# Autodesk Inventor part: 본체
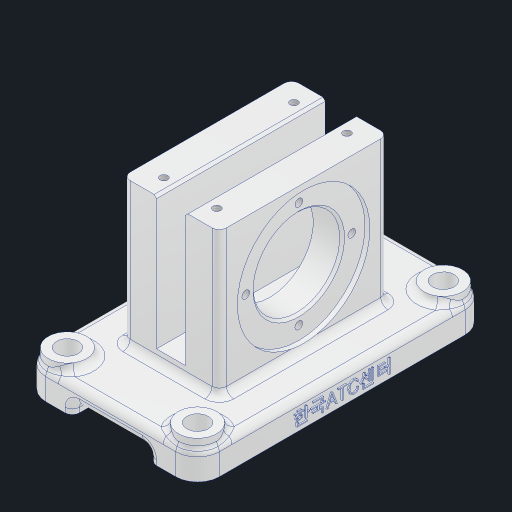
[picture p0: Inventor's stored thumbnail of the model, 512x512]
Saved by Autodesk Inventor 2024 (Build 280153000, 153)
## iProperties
Created: 2025-04
Part Number: 본체
Material: 알루미늄 6061
Document SubType Name: Modeling
Designer: kh_501
Density: 2.7 g/cm^3
Appearance: 알루미늄 - 평지
Mass: 493.657 g
Surface Area: 439.689 cm^2
Volume: 182.836 cm^3
Author: kh_501
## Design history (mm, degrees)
sketch "스케치1"
  geometry: L1 (36, 60)-(-36, 60); L2 (-36, 60)-(-36, -60); L3 (-36, -60)-(36, -60); L4 (36, -60)-(36, 60); L5 (36, 60)-(-36, -60); L6 (-36, 60)-(36, -60); 1 further point
  constraints: 12 end point, 2 midpoint, 2 parallel, 1 horizontal, 1 perpendicular
  dimensions: "d0" = 120 distance of L3.end L1.start; "d1" = 72 distance of L2.end L3.end
extrude "돌출1" new body sketch "스케치1" distance "d2" = 12; taper "d3" = 0 deg
sketch "스케치2"
  geometry: L1 (72, 35)-(12, 35); L2 (12, 35)-(12, -35); L3 (12, -35)-(72, -35); L4 (72, -35)-(72, 35); L5 (12, 60)-(12, -60) reference; L6 (0, 60)-(0, -60) reference; 2 further points
  constraints: 8 end point, 2 midpoint, 2 parallel, 1 horizontal, 1 perpendicular
  dimensions: "d4" = 70 distance of L3.end L1.start; "d5" = 72 distance between parallel lines of L6 L4
extrude "돌출2" join sketch "스케치2" stored distance "d6" = 40; taper "d7" = 0 deg
sketch "스케치3"
  geometry: L1 (14, 60)-(26, 60); L2 (26, 60)-(26, 5); L3 (26, 5)-(14, 5); L4 (14, 5)-(14, 60); L5 (40, 60)-(0, 60) reference; 3 further points
  constraints: 8 end point, 3 midpoint, 2 parallel, 1 horizontal, 1 perpendicular
  dimensions: "d8" = 12 distance from line of point (26, 32.5) L4; "d9" = 55 distance of L1.end L2.end
extrude "돌출3" cut sketch "스케치3" extent not by distance; stored distance "d10" = 0; taper "d11" = 0 deg
sketch "스케치4"
  geometry: L1 (-60, 0)-(60, 0) reference; C1 r 17 at (0, 42); 2 further points
  constraints: 1 centre point, 1 midpoint, 1 vertical alignment
  dimensions: "d12" = 34 diameter of C1; "d13" = 42 distance from line of C1.centre L1
extrude "돌출4" join sketch "스케치4" distance "d14" = 7; taper "d15" = 0 deg
sketch "스케치5"
  geometry: L1 (20, 72)-(20, 12) reference; L2 (-27, 59)-(-27, 25) reference; L3 (-27, 42)-(20, 42); L4 (20, 69.5)-(18, 69.5); L5 (18, 69.5)-(18, 61); L6 (17, 60)-(6, 60); L7 (6, 72)-(6, 17) reference; L8 (-6, 17)-(-6, 72) reference; L9 (-6, 57)-(-11, 57); L10 (-11, 57)-(-11, 54); L11 (-12, 53)-(-27, 53); L12 (-11, 54)-(-12, 53); L13 (18, 61)-(17, 60); 6 further points
  constraints: 18 end point, 8 point on line, 4 perpendicular, 3 midpoint, 2 horizontal
  dimensions: "d16" = 22 diameter of L11 L3; "d17" = 30 diameter of L9 L3; "d18" = 5 distance of L9.start L9.end; "d19" = 2 distance of L4.start L4.end; "d20" = 36 diameter of L6 L3; "d21" = 55 diameter of point (19, 69.5) L3; "d22" = 1 distance of L10.end point (-11, 53); "d23" = 1 distance of L11.start point (-11, 53) (= d22); "d24" = 1 distance of L5.end point (18, 60) (= d22); "d25" = 1 distance of L6.start point (18, 60) (= d24)
revolve "회전1" sketch "스케치5" stored, may be unused: angle "d26" = 90 deg
sketch "스케치6" dims "d27" = 44
  geometry: L1 (0, 0)-(0, 22); C1 r 27.5 at (0, 0) reference; 2 further points
  constraints: 2 coincident, 2 end point, 1 vertical, 1 vertical alignment, 2 other
hole "구멍1" sketch "스케치6" at (0, 22) diameter "d28" = 3.242; stored, may be unused: countersink angle "d32" = 90 deg, drill point angle "d34" = 118 deg; dims "d29" = 8, "d30" = 4, "d31" = 2, "d33" = 10
sketch "스케치7"
  geometry: L1 (31, 62)-(9, 62); L2 (9, 62)-(9, 8); L3 (9, 8)-(31, 8); L4 (31, 8)-(31, 62); L5 (31, 62)-(9, 8); L6 (9, 62)-(31, 8); 5 further points
  constraints: 12 end point, 4 coincident, 2 midpoint, 2 parallel, 1 horizontal, 1 perpendicular
  dimensions: "d38" = 54 distance of L3.end L1.start; "d39" = 22 distance of L2.end L3.end
hole "구멍2" sketch "스케치7" at (31, 62), (9, 62), (31, 8), (9, 8) diameter "d40" = 3.242; stored, may be unused: countersink angle "d44" = 90 deg, drill point angle "d46" = 118 deg; dims "d41" = 8, "d42" = 4, "d43" = 2, "d45" = 10
node "작업 평면1"
sketch "스케치8"
  geometry: 1 further point
fillet "모깎기1" dims "d48" = 9
chamfer "모따기1" distance "d51" = 1; stored, may be unused: second distance "d52" = 2, angle "d53" = 45 deg
fillet "모깎기4" dims "d54" = 3
sketch "스케치9"
  geometry: L1 (11, 5)-(43, 5); L2 (43, 5)-(43, 0); L3 (43, 0)-(11, 0); L4 (11, 0)-(11, 5); L5 (0, 0)-(54, 0) reference; 2 further points
  constraints: 8 end point, 2 midpoint, 2 parallel, 1 horizontal, 1 perpendicular
  dimensions: "d55" = 32 distance of L2.end L3.end; "d56" = 5 distance of L1.end L2.end
extrude "돌출5" cut sketch "스케치9" extent not by distance; stored distance "d57" = 0; taper "d58" = 0 deg
sketch "스케치10"
  geometry: L1 (27, 51)-(-27, 51); L2 (-27, 51)-(-27, -51); L3 (-27, -51)-(27, -51); L4 (27, -51)-(27, 51); L5 (27, 51)-(-27, -51); L6 (-27, 51)-(27, -51); C1 r 8 at (27, 51); C2 r 8 at (-27, 51); C3 r 8 at (27, -51); C4 r 8 at (-27, -51); C5 r 4.5 at (27, 51); C6 r 4.5 at (-27, 51); C7 r 4.5 at (-27, -51); C8 r 4.5 at (27, -51); 1 further point
  constraints: 12 end point, 8 centre point, 8 coincident, 2 midpoint, 2 parallel, 1 horizontal, 1 perpendicular
  dimensions: "d59" = 102 distance of L3.end L1.start; "d60" = 54 distance of L2.end L3.end; "d61" = 16 diameter of C1; "d62" = 16 diameter of C2; "d63" = 16 diameter of C3; "d64" = 16 diameter of C4; "d71" = 9 diameter of C5; "d72" = 9 diameter of C6; "d73" = 9 diameter of C7; "d74" = 9 diameter of C8
extrude "돌출6" join sketch "스케치10" stored distance "d67" = 10; taper "d68" = 0 deg
fillet "모깎기5" dims "d69" = 3
fillet "모깎기6" dims "d70" = 3
extrude "돌출7" cut sketch "스케치10" extent not by distance; stored distance "d75" = 0; taper "d76" = 0 deg
fillet "모깎기7" dims "d77" = 3
fillet "모깎기8" dims "d78" = 3
fillet "모깎기9" dims "d79" = 3
fillet "모깎기10" dims "d80" = 3
fillet "모깎기11" dims "d81" = 3
sketch "스케치11" dims "d0" = 120, "d1" = 72
  geometry: L1 (0, 0)-(102, 0) reference; 3 further points
  constraints: 1 midpoint, 1 vertical alignment, 1 other
  dimensions: "d82" = 5 distance from line of point (51, 5) L1
feature "엠보싱1" sketch "스케치11" dims "d0" = 120, "d1" = 72, "d83" = 0.5, "d84" = 0
feature "ϓ耀ϕ耀ϗ耀ϙ耀ϛ耀ϝ耀ϟ耀ϡ耀" dims "d0" = 120, "d1" = 72, "d2" = 12, "d3" = 0, "d4" = 70, "d5" = 72, "d6" = 40, "d7" = 0, "d8" = 12, "d9" = 55, "d10" = 0, "d11" = 0, "d12" = 34, "d13" = 42, "d14" = 7, "d15" = 0, "d16" = 22, "d17" = 30, "d18" = 5, "d19" = 2, "d20" = 36, "d21" = 55, "d22" = 1, "d23" = 1 (= d22)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
node "솔리드1"
pattern_circular "원형 패턴1" dims angle "d36" = 360 deg
feature "A9D066F2-1C7D-4E18-AEED-F7BC21143FA4" dims "d28" = 3.242, "d29" = 8, "d30" = 4, "d31" = 2, "d32" = 90 deg, "d33" = 10, "d34" = 118 deg
